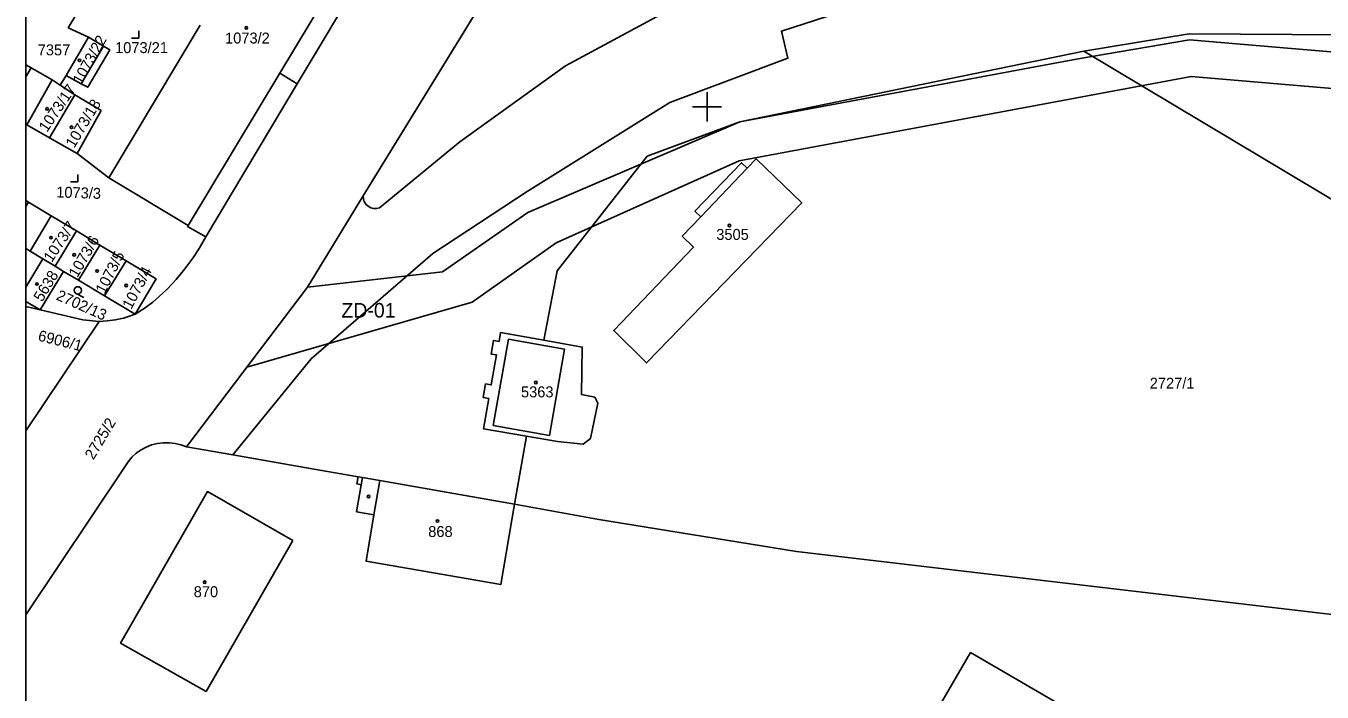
# Model space of a CAD drawing. Extents: x -800194 to -799297, y -1007177 to -1006761.
# Drawn here: x -800193.4 to -800015.7, y -1006980.2 to -1006888.9 of the extents above; entities that cross this region are included whole.
import ezdxf

# ---------------------------------------------------------------- set-up
doc = ezdxf.new("R2010")
doc.units = 0
for name, color, linetype in [('Dočasné zábory', 7, 'Continuous'), ('Dočasné zábory - čísla', 7, 'Continuous'), ('Legenda 1', 7, 'Continuous'), ('Ramove udaje', 7, 'Continuous'), ('Vrstva 53', 7, 'Continuous'), ('Vrstva 55', 7, 'Continuous'), ('Vrstva 56', 7, 'Continuous'), ('Vrstva 57', 7, 'Continuous'), ('Vrstva 58', 7, 'Continuous'), ('Vrstva 59', 7, 'Continuous')]:
    doc.layers.add(name, color=color, linetype=linetype)

msp = doc.modelspace()

# ---------------------------------------------------------------- linework, layer by layer
at = {"layer": 'Dočasné zábory'}
msp.add_lwpolyline([(-799842.29, -1006982.66), (-799850.11, -1006971.65), (-799855.04, -1006966.34), (-799934.68, -1006921.09), (-799969.58, -1006905.87), (-799994.89, -1006899.12), (-800033.61, -1006895.83), (-800095.58, -1006907.39), (-800120.68, -1006918.64), (-800132.21, -1006926.78), (-800163.09, -1006935.68), (-800154.78, -1006924.73), (-800136.27, -1006922.64), (-800124.59, -1006914.47), (-800095.49, -1006902.03), (-800049.12, -1006893.41), (-800033.82, -1006890.8), (-799994.03, -1006894.18), (-799967.93, -1006901.13), (-799932.44, -1006916.61), (-799851.52, -1006962.6), (-799838.48, -1006981.29), (-799834.59, -1006980.15), (-799830.67, -1006986.18)], dxfattribs=at)
at = {"layer": 'Legenda 1'}
msp.add_lwpolyline([(-800193.4, -1007176.65), (-799312.4, -1007176.65), (-799312.4, -1006766.65), (-800193.4, -1006766.65)], close=True, dxfattribs=at)
at = {"layer": 'Ramove udaje'}
for p, q in [((-800100, -1006898), (-800100, -1006902)), ((-800102, -1006900), (-800100, -1006900)), ((-800100, -1006900), (-800098, -1006900))]:
    msp.add_line(p, q, dxfattribs=at)
at = {"layer": 'Vrstva 53'}
msp.add_lwpolyline([(-800101.58, -1006884.73), (-800119.41, -1006894.35), (-800133.89, -1006904.78), (-800144.92, -1006913.85), (-800145.32, -1006913.94), (-800145.72, -1006913.94), (-800146.12, -1006913.83), (-800146.47, -1006913.63), (-800146.77, -1006913.35), (-800147, -1006912.99), (-800147.12, -1006912.61), (-800147.15, -1006912.2), (-800112.81, -1006856.29)], dxfattribs=at)
at = {"layer": 'Vrstva 55'}
for p, q in [((-800186.55, -1006887.44), (-800187.59, -1006889.15)), ((-800187.59, -1006889.15), (-800184.82, -1006890.46)), ((-800169.49, -1006888.81), (-800182.05, -1006909.75)), ((-800184.82, -1006890.46), (-800187.9, -1006895.7)), ((-799905.8, -1006977.56), (-800048.34, -1006892.35)), ((-800192.7, -1006894.63), (-800193.4, -1006894.24)), ((-800193.4, -1006895.86), (-800192.7, -1006894.63)), ((-800193.28, -1006902.47), (-800189.78, -1006896.28)), ((-800189.78, -1006896.28), (-800192.7, -1006894.63)), ((-800188.68, -1006897.03), (-800189.78, -1006896.28)), ((-800187.9, -1006895.7), (-800188.68, -1006897.03)), ((-800186.7, -1006898.36), (-800188.68, -1006897.03)), ((-800190.15, -1006904.25), (-800186.7, -1006898.36)), ((-800183.1, -1006900.51), (-800186.7, -1006898.36)), ((-800186.38, -1006906.38), (-800183.1, -1006900.51)), ((-800193.28, -1006902.47), (-800193.4, -1006902.4)), ((-800190.15, -1006904.25), (-800193.28, -1006902.47)), ((-800186.38, -1006906.38), (-800190.15, -1006904.25)), ((-800182.05, -1006909.75), (-800186.38, -1006906.38)), ((-800193.05, -1006913.06), (-800193.4, -1006913.64)), ((-800193.05, -1006913.06), (-800189.92, -1006914.94)), ((-800189.92, -1006914.94), (-800192.83, -1006919.78)), ((-800189.92, -1006914.94), (-800186.48, -1006917.01)), ((-800186.48, -1006917.01), (-800189.39, -1006921.85)), ((-800186.48, -1006917.01), (-800183.26, -1006918.94)), ((-800183.26, -1006918.94), (-800186.17, -1006923.78)), ((-800183.26, -1006918.94), (-800179.67, -1006921.09)), ((-800193.4, -1006919.44), (-800192.83, -1006919.78)), ((-800191.06, -1006920.85), (-800193.4, -1006924.74)), ((-800192.83, -1006919.78), (-800191.06, -1006920.85)), ((-800191.06, -1006920.85), (-800189.39, -1006921.85)), ((-800179.67, -1006921.09), (-800182.6, -1006925.93)), ((-800188.23, -1006922.55), (-800191.44, -1006927.83)), ((-800189.39, -1006921.85), (-800188.23, -1006922.55)), ((-800188.23, -1006922.55), (-800186.17, -1006923.78)), ((-800120.56, -1006922.5), (-800122.37, -1006932)), ((-800186.17, -1006923.78), (-800182.6, -1006925.93)), ((-800182.6, -1006925.93), (-800178.43, -1006928.42)), ((-800191.44, -1006927.83), (-800193.4, -1006926.67)), ((-800191.44, -1006927.83), (-800193.4, -1006927.37)), ((-800183.37, -1006929.41), (-800193.4, -1006944.43)), ((-800124.76, -1006945.16), (-800126.38, -1006954.46)), ((-800165.04, -1006947.7), (-800171.39, -1006946.62))]:
    msp.add_line(p, q, dxfattribs=at)
for points in [[(-800147.15, -1006912.2), (-800114.97, -1006859.8), (-800112.81, -1006856.29)], [(-800144.92, -1006913.85), (-800133.89, -1006904.78), (-800119.41, -1006894.35), (-800101.58, -1006884.73), (-800082.93, -1006877.89), (-800083.75, -1006874.38)], [(-799964.79, -1006890.84), (-799979.01, -1006885.96), (-799998.45, -1006881.67), (-800018.08, -1006879.48), (-800038.51, -1006879.76), (-800056.43, -1006881.95), (-800070.76, -1006884.38), (-800080.47, -1006886.59), (-800089.79, -1006889.63), (-800088.91, -1006893.34), (-800105.12, -1006899.41), (-800124.67, -1006911.59), (-800137.62, -1006920.11), (-800154.3, -1006934.53), (-800165.04, -1006947.7)], [(-800146.81, -1006881.14), (-800156.19, -1006896.85), (-800168.72, -1006917.84)], [(-800184.82, -1006890.46), (-800182.76, -1006891.66), (-800181.9, -1006892.16), (-800184.93, -1006897.3), (-800185.8, -1006896.83), (-800187.9, -1006895.7)], [(-799901.69, -1006974.63), (-799900.54, -1006973.82), (-799898.31, -1006947.43), (-799904.63, -1006933.89), (-799915, -1006924.46), (-799932.22, -1006915.03), (-799953.17, -1006905.18), (-799968.93, -1006898.86), (-799993.08, -1006892.39), (-800012.71, -1006890.11), (-800033.89, -1006890), (-800048.34, -1006892.35)], [(-800048.34, -1006892.35), (-800095.49, -1006902.03), (-800108.2, -1006906.76), (-800120.56, -1006922.5)], [(-800094.49, -1006908.41), (-800093.24, -1006907.11), (-800087, -1006913.15), (-800108.28, -1006935.11), (-800112.78, -1006930.68), (-800101.83, -1006919.22), (-800103.39, -1006917.73), (-800100.86, -1006915.08), (-800101.66, -1006914.32), (-800095.28, -1006907.65), (-800094.49, -1006908.41)], [(-800182.05, -1006909.75), (-800171.15, -1006916.28), (-800171.22, -1006916.39), (-800168.72, -1006917.84)], [(-800171.39, -1006946.62), (-800154.78, -1006924.73), (-800147.15, -1006912.2)], [(-800147.15, -1006912.2), (-800147.12, -1006912.61), (-800147, -1006912.99), (-800146.78, -1006913.34), (-800146.77, -1006913.35), (-800146.47, -1006913.63), (-800146.12, -1006913.83), (-800145.72, -1006913.94), (-800145.32, -1006913.94), (-800144.92, -1006913.85)], [(-800193.4, -1006912.85), (-800193.05, -1006913.06)], [(-800168.72, -1006917.84), (-800169.66, -1006919.43), (-800170.52, -1006920.73), (-800171.62, -1006922.22), (-800172.79, -1006923.65), (-800174.04, -1006925.01), (-800175.11, -1006926.02), (-800176, -1006926.76), (-800177.19, -1006927.63), (-800178.43, -1006928.42)], [(-800179.67, -1006921.09), (-800175.54, -1006923.58), (-800178.43, -1006928.42)], [(-800183.37, -1006929.41), (-800185.59, -1006929.21), (-800191.44, -1006927.83)], [(-800178.43, -1006928.42), (-800179.48, -1006928.81), (-800180.04, -1006928.97), (-800181.14, -1006929.22), (-800182.25, -1006929.36), (-800183.37, -1006929.41)], [(-800124.76, -1006945.16), (-800130.67, -1006944.14), (-800129.93, -1006939.99), (-800130.7, -1006939.85), (-800130.36, -1006937.99), (-800129.59, -1006938.12), (-800128.86, -1006934.02), (-800129.62, -1006933.9), (-800129.29, -1006932.03), (-800128.52, -1006932.16), (-800128.31, -1006930.95), (-800122.37, -1006932)], [(-800122.37, -1006932), (-800117.1, -1006932.94), (-800117.23, -1006939.43), (-800115.39, -1006939.82), (-800114.95, -1006940.64), (-800115.98, -1006945.49), (-800117, -1006946.26), (-800120.48, -1006945.9), (-800124.76, -1006945.16)], [(-800179.84, -1006949.35), (-800179.39, -1006948.67), (-800178.86, -1006948.05), (-800178.26, -1006947.5), (-800177.6, -1006947.03), (-800176.89, -1006946.65), (-800176.16, -1006946.36), (-800175.37, -1006946.16), (-800174.56, -1006946.05), (-800173.75, -1006946.05), (-800172.94, -1006946.14), (-800172.15, -1006946.33), (-800171.39, -1006946.62)], [(-800165.04, -1006947.7), (-800154.15, -1006949.62), (-800147.83, -1006950.72)], [(-800193.4, -1006969.65), (-800179.84, -1006949.35)], [(-800147.83, -1006950.72), (-800148, -1006951.71), (-800147.41, -1006951.81), (-800148.05, -1006955.52), (-800145.68, -1006955.92), (-800146.75, -1006962.28), (-800128.29, -1006965.5), (-800126.38, -1006954.46)], [(-800147.83, -1006950.72), (-800147.24, -1006950.83), (-800144.85, -1006951.24), (-800126.38, -1006954.46)], [(-800156.78, -1006959.44), (-800168.69, -1006980.17), (-800180.42, -1006973.53), (-800168.51, -1006952.75), (-800156.78, -1006959.44)], [(-800126.38, -1006954.46), (-800114.82, -1006956.57), (-800087.75, -1006960.99), (-799990.59, -1006972.38), (-799910.85, -1006981.15)], [(-800069.59, -1006984.65), (-800063.85, -1006974.82), (-800037.33, -1006990.25), (-800033.78, -1006992.42), (-800023.89, -1006998.18), (-800020.27, -1007000.33), (-799995.43, -1007014.87), (-800001.26, -1007024.83), (-800026.05, -1007010.11), (-800029.71, -1007008.06), (-800039.6, -1007002.32), (-800043.23, -1007000.2), (-800069.59, -1006984.65)]]:
    msp.add_lwpolyline(points, dxfattribs=at)
at = {"layer": 'Vrstva 56'}
for p, q in [((-800149.24, -1006879.83), (-800158.6, -1006895.39)), ((-800182.76, -1006891.66), (-800185.8, -1006896.83)), ((-800158.6, -1006895.39), (-800171.15, -1006916.28)), ((-800158.6, -1006895.39), (-800156.19, -1006896.85)), ((-800100.86, -1006915.08), (-800094.49, -1006908.41)), ((-800127.23, -1006931.83), (-800129.33, -1006943.68)), ((-800119.52, -1006933.21), (-800127.23, -1006931.83)), ((-800121.59, -1006945.08), (-800119.52, -1006933.21)), ((-800129.33, -1006943.68), (-800121.59, -1006945.08)), ((-800147.41, -1006951.81), (-800147.24, -1006950.83)), ((-800145.68, -1006955.92), (-800144.85, -1006951.24))]:
    msp.add_line(p, q, dxfattribs=at)
at = {"layer": 'Vrstva 58'}
for p, q in [((-800178.93, -1006890.56), (-800177.92, -1006890.56)), ((-800177.92, -1006890.56), (-800177.92, -1006889.56)), ((-800187.28, -1006910.27), (-800186.28, -1006910.27)), ((-800186.28, -1006910.27), (-800186.28, -1006909.27)), ((-800186.51, -1006925.6), (-800185.47, -1006926.15))]:
    msp.add_line(p, q, dxfattribs=at)
msp.add_circle((-800186.27, -1006925.16), 0.502, dxfattribs=at)
at = {"layer": 'Vrstva 59'}
for centre in [(-800163.18, -1006889.16), (-800186.06, -1006893.62), (-800190.48, -1006900.28), (-800187.14, -1006902.79), (-800096.93, -1006916.27), (-800189.96, -1006917.94), (-800186.79, -1006920.28), (-800183.63, -1006922.51), (-800191.89, -1006924.28), (-800179.65, -1006924.5), (-800123.47, -1006937.8), (-800146.41, -1006953.43), (-800136.95, -1006956.79), (-800168.88, -1006965.17)]:
    msp.add_circle(centre, 0.175, dxfattribs=at)

# ---------------------------------------------------------------- texts
at = {"layer": 'Dočasné zábory - čísla'}
msp.add_text('ZD-01', height=2, rotation=0, dxfattribs=at).set_placement((-800150.14, -1006928.89))
at = {"layer": 'Vrstva 57'}
for s, rotation, p in [('1073/22', 61, (-800185.78, -1006897.06)), ('1073/17', 56, (-800190.51, -1006903.56)), ('1073/18', 59, (-800186.78, -1006905.74)), ('1073/3', 358, (-800189.26, -1006912.41)), ('1073/7', 56, (-800189.86, -1006921.42)), ('1073/6', 60, (-800186.35, -1006923.53)), ('1073/5', 63, (-800182.61, -1006925.75)), ('5638', 59, (-800191.17, -1006926.84)), ('1073/4', 62, (-800178.95, -1006927.85)), ('2702/13', 336, (-800189.37, -1006926.38)), ('6906/1', 346, (-800191.84, -1006932.03)), ('2725/2', 59, (-800184.15, -1006948.49))]:
    msp.add_text(s, height=1.5, rotation=rotation, dxfattribs=at).set_placement(p)
for s, p in [('1073/2', (-800166.09, -1006891.31)), ('7357', (-800191.78, -1006892.93)), ('1073/21', (-800181.17, -1006892.62)), ('3505', (-800098.73, -1006918.24)), ('2727/1', (-800039.29, -1006938.64)), ('5363', (-800125.51, -1006939.83)), ('868', (-800138.23, -1006958.98)), ('870', (-800170.39, -1006967.23))]:
    msp.add_text(s, height=1.5, dxfattribs=at).set_placement(p)

doc.saveas('drawing.dxf')
